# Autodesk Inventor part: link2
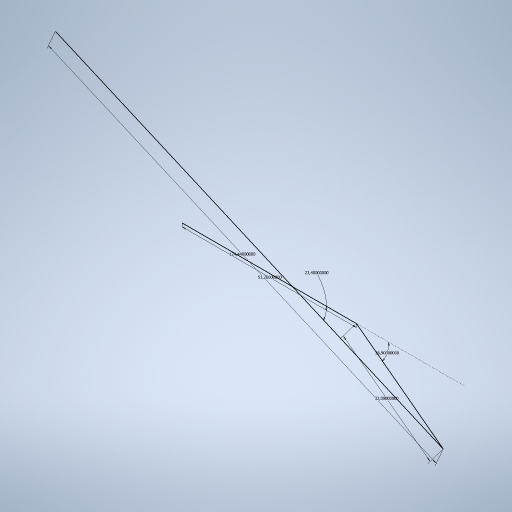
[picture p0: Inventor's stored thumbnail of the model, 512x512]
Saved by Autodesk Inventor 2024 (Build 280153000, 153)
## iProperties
Created: 2023-10
Part Number: link2
Material: Generic
Document SubType Name: Modeling
Designer: ESTUDIANTE
Density: 1 g/cm^3
Appearance: Default
Author: ESTUDIANTE
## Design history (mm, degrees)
sketch "Sketch2"
  geometry: L1 (0, 0)-(1302.004, 0); L2 (1302.004, 0)-(1951.988, -488.022); L3 (1302.004, 0)-(2114.804, 0); L4 (1951.988, -488.022)-(-948.829, 767.274)
  constraints: 8 end point, 2 horizontal, 1 equal length
  dimensions: "d2" = 1302.004 distance of L1.start L1.end; "d3" = 812.8 distance of L1.end L2.end; "d4" = 36.9 deg angle of L2 L3; "d5" = 3160.776 distance of L2.end L4.end; "d6" = 156.6 deg angle of L4 L1
